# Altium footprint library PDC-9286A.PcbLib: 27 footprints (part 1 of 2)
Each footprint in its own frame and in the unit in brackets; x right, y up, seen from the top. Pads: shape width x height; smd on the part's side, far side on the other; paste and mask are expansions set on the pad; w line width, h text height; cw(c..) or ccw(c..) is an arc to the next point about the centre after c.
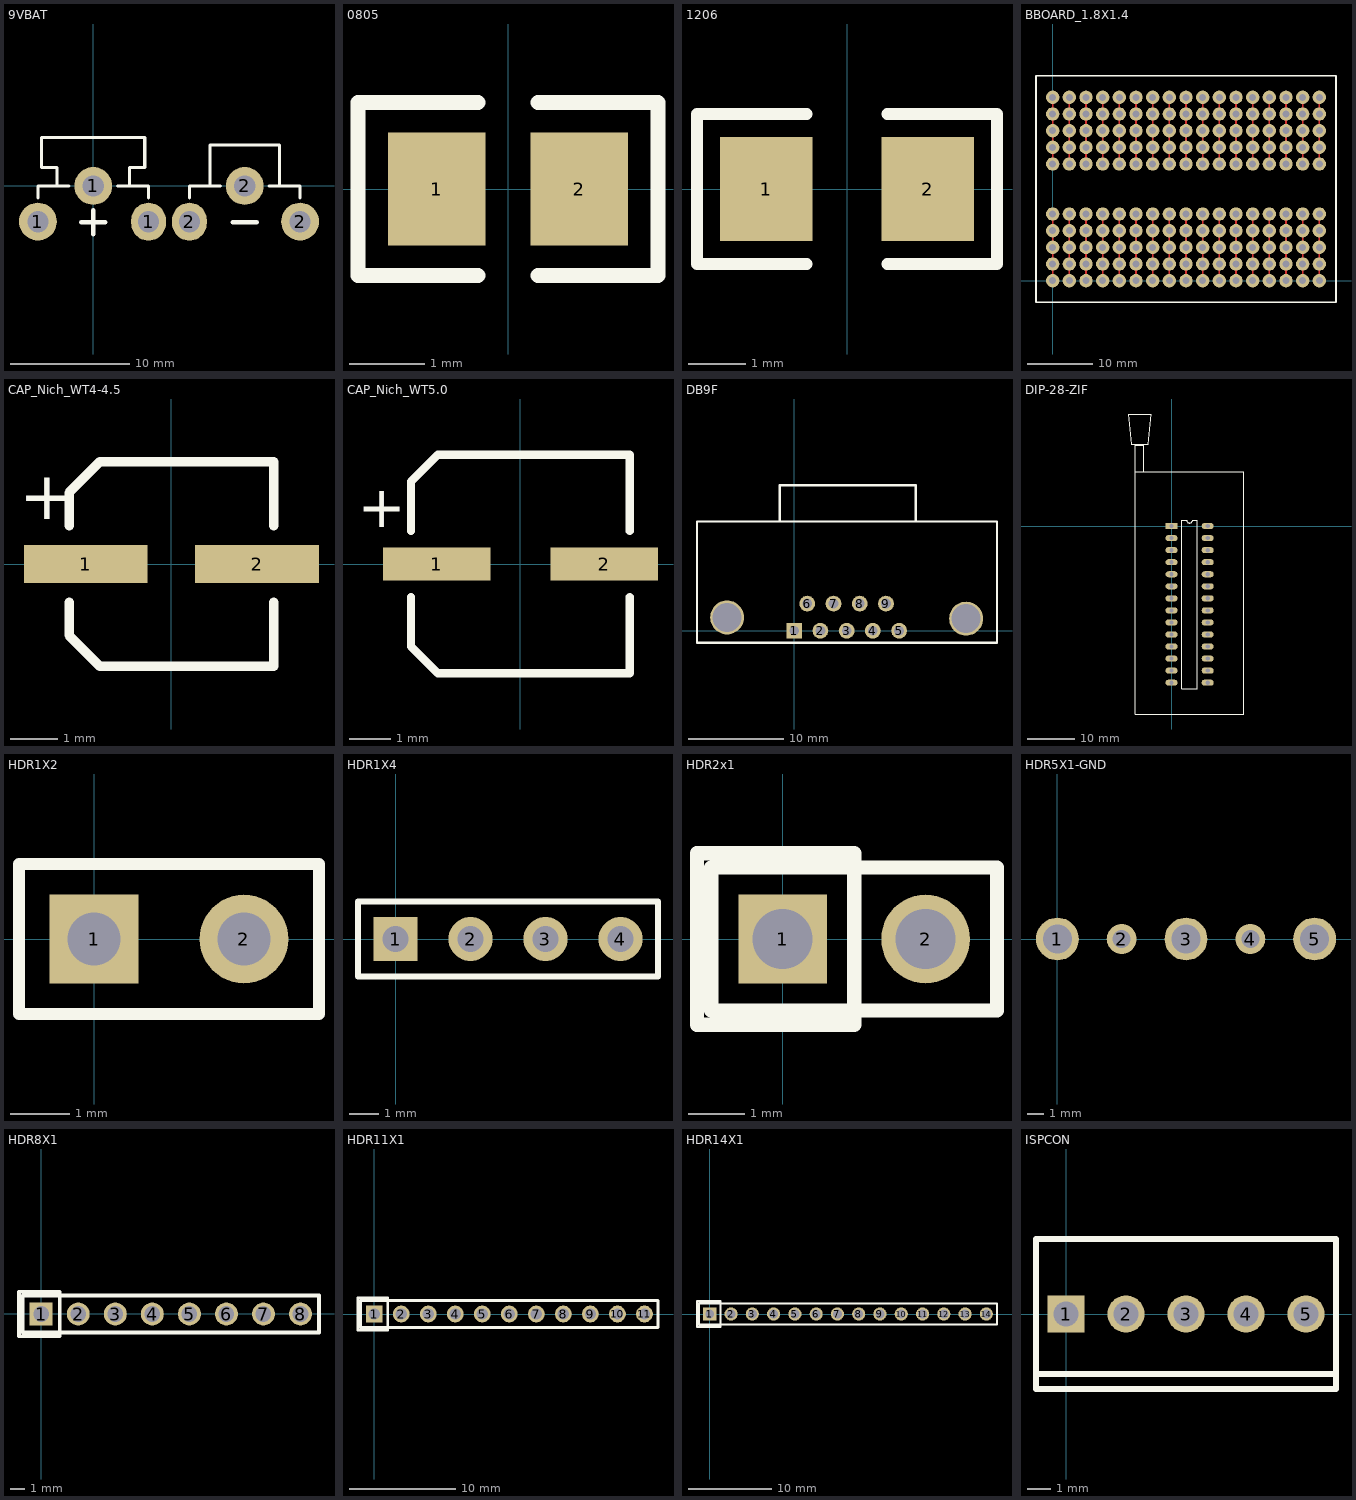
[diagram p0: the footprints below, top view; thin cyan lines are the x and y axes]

## 9VBAT [mil]
pads (6):
  round 125 hole 70: 1(-182.5,-118) 1(0,0) 2(500,0) 2(682.5,-118)
  oval 115x125 hole 70: 1(182.5,-118) 2(317.5,-118)
Top Overlay:
  lines w10: -182.5,-40 -182.5,0 -80,0 ; -120,0 -120,60 -170,60 -170,160 170,160 170,60 120,60 120,0 ; 80,0 182.5,0 182.5,-40 ; 317.5,-40 317.5,0 420,0 ; 385,0 385,135 615,135 615,0 ; 580,0 682.5,0 682.5,-40
  lines w15: -40,-120 40,-120 ; 0,-160 0,-80 ; 460,-120 540,-120

## 0805 [mm]
pads (2):
  rect 1.3x1.5 smd: 1(-0.95,0) 2(0.95,0)
Top Overlay:
  lines w0.2: -0.4,-1.15 -2,-1.15 -2,1.15 -0.4,1.15 ; 0.4,-1.15 2,-1.15 2,1.15 0.4,1.15

## 1206 [mm]
pads (2):
  rect 1.6x1.8 smd: 1(-1.4,0) 2(1.4,0)
Top Overlay:
  lines w0.2: -0.7,-1.3 -2.6,-1.3 -2.6,1.3 -0.7,1.3 ; 0.7,-1.3 2.6,-1.3 2.6,1.3 0.7,1.3

## BBOARD_1.8X1.4 [mil] "28 tie point Breadboard  ( 3M 923273-I )"
pads (170):
  round 80 hole 42: ""(0,0) ""(0,100) ""(0,200) ""(0,300) ""(0,400) ""(0,700) ""(0,800) ""(0,900) ""(0,1000) ""(0,1100) ""(100,0) ""(100,100) ""(100,200) ""(100,300) ""(100,400) ""(100,700) ""(100,800) ""(100,900) ""(100,1000) ""(100,1100) ""(200,0) ""(200,100) ""(200,200) ""(200,300) ""(200,400) ""(200,700) ""(200,800) ""(200,900) ""(200,1000) ""(200,1100) ""(300,0) ""(300,100) ""(300,200) ""(300,300) ""(300,400) ""(300,700) ""(300,800) ""(300,900) ""(300,1000) ""(300,1100) ""(400,0) ""(400,100) ""(400,200) ""(400,300) ""(400,400) ""(400,700) ""(400,800) ""(400,900) ""(400,1000) ""(400,1100) ""(500,0) ""(500,100) ""(500,200) ""(500,300) ""(500,400) ""(500,700) ""(500,800) ""(500,900) ""(500,1000) ""(500,1100) ""(600,0) ""(600,100) ""(600,200) ""(600,300) ""(600,400) ""(600,700) ""(600,800) ""(600,900) ""(600,1000) ""(600,1100) ""(700,0) ""(700,100) ""(700,200) ""(700,300) ""(700,400) ""(700,700) ""(700,800) ""(700,900) ""(700,1000) ""(700,1100) ""(800,0) ""(800,100) ""(800,200) ""(800,300) ""(800,400) ""(800,700) ""(800,800) ""(800,900) ""(800,1000) ""(800,1100) ""(900,0) ""(900,100) ""(900,200) ""(900,300) ""(900,400) ""(900,700) ""(900,800) ""(900,900) ""(900,1000) ""(900,1100) ""(1000,0) ""(1000,100) ""(1000,200) ""(1000,300) ""(1000,400) ""(1000,700) ""(1000,800) ""(1000,900) ""(1000,1000) ""(1000,1100) ""(1100,0) ""(1100,100) ""(1100,200) ""(1100,300) ""(1100,400) ""(1100,700) ""(1100,800) ""(1100,900) ""(1100,1000) ""(1100,1100) ""(1200,0) ""(1200,100) ""(1200,200) ""(1200,300) ""(1200,400) ""(1200,700) ""(1200,800) ""(1200,900) ""(1200,1000) ""(1200,1100) ""(1300,0) ""(1300,100) ""(1300,200) ""(1300,300) ""(1300,400) ""(1300,700) ""(1300,800) ""(1300,900) ""(1300,1000) ""(1300,1100) ""(1400,0) ""(1400,100) ""(1400,200) ""(1400,300) ""(1400,400) ""(1400,700) ""(1400,800) ""(1400,900) ""(1400,1000) ""(1400,1100) ""(1500,0) ""(1500,100) ""(1500,200) ""(1500,300) ""(1500,400) ""(1500,700) ""(1500,800) ""(1500,900) ""(1500,1000) ""(1500,1100) ""(1600,0) ""(1600,100) ""(1600,200) ""(1600,300) ""(1600,400) ""(1600,700) ""(1600,800) ""(1600,900) ""(1600,1000) ""(1600,1100)
Top Layer:
  lines w10: 0,0 0,400 ; 0,700 0,1100 ; 100,0 100,400 ; 100,700 100,1100 ; 200,0 200,400 ; 200,700 200,1100 ; 300,0 300,400 ; 300,700 300,1100 ; 400,0 400,400 ; 400,700 400,1100 ; 500,0 500,400 ; 500,700 500,1100 ; 600,0 600,400 ; 600,700 600,1100 ; 700,0 700,400 ; 700,700 700,1100 ; 800,0 800,400 ; 800,700 800,1100 ; 900,0 900,400 ; 900,700 900,1100 ; 1000,0 1000,400 ; 1000,700 1000,1100 ; 1100,0 1100,400 ; 1100,700 1100,1100 ; 1200,0 1200,400 ; 1200,700 1200,1100 ; 1300,0 1300,400 ; 1300,700 1300,1100 ; 1400,0 1400,400 ; 1400,700 1400,1100 ; 1500,0 1500,400 ; 1500,700 1500,1100 ; 1600,0 1600,400 ; 1600,700 1600,1100
Top Overlay:
  lines w10: -100,-130 -100,1230 1700,1230 1700,-130 -100,-130

## CAP_Nich_WT4-4.5 [mm]
pads (2):
  rect 2.6x0.8 smd: 1(-1.8,0) 2(1.8,0)
Top Overlay:
  lines w0.2: -2.15,-0.8 -2.15,-1.5 -1.5,-2.15 2.15,-2.15 2.15,-0.8 ; -2.15,0.8 -2.15,1.5 -1.5,2.15 2.15,2.15 2.15,0.8
  text "+" at -3.2,0.94 h1.02

## CAP_Nich_WT5.0 [mm]
pads (2):
  rect 2.6x0.8 smd: 1(-2.032,0) 2(2.032,0)
Top Overlay:
  lines w0.2: -2.65,-0.8 -2.65,-2 -2,-2.65 2.65,-2.65 2.65,-0.8 ; -2.65,0.8 -2.65,2 -2,2.65 2.65,2.65 2.65,0.8
  text "+" at -3.937,0.889 h1.02

## DB9F [mil]
pads (11):
  rect 65x65 hole 40: 1(0,0)
  round 65 hole 40: 2(108,0) 3(216,0) 4(324,0) 5(432,0) 6(54,112) 7(162,112) 8(270,112) 9(378,112)
  round 140 hole 120: ""(-276,55) ""(708,50)
Top Overlay:
  lines w10: -60,450 -60,600 500,600 500,450 ; -400,-50 835,-50 835,450 -400,450 -400,-50

## DIP-28-ZIF [mil]
pads (28):
  rect 100x50 hole 35: 1(0,0)
  oval 100x50 hole 35: 2(0,-100) 3(0,-200) 4(0,-300) 5(0,-400) 6(0,-500) 7(0,-600) 8(0,-700) 9(0,-800) 10(0,-900) 11(0,-1000) 12(0,-1100) 13(0,-1200) 14(0,-1300) 15(300,-1300) 16(300,-1200) 17(300,-1100) 18(300,-1000) 19(300,-900) 20(300,-800) 21(300,-700) 22(300,-600) 23(300,-500) 24(300,-400) 25(300,-300) 26(300,-200) 27(300,-100) 28(300,0)
Top Overlay:
  lines w10: -230,450 -230,670 -300,670 -300,450 ; -300,450 600,450 600,-1560 -300,-1560 -300,450 ; -360,930 -335,680 -195,680 -170,930 -360,930 ; 85,-1350 85,50 125,50 ccw(c150,50) 175,50 215,50 215,-1350 85,-1350

## HDR1X2 [mm] "Connector; Header; 2 Position"
pads (2):
  rect 1.5x1.5 hole 0.9: 1(0,0)
  round 1.5 hole 0.9: 2(2.54,0)
Top Overlay:
  lines w0.2: -1.27,-1.27 3.81,-1.27 3.81,1.27 -1.27,1.27 -1.27,-1.27

## HDR1X4 [mm] "Connector; Header; 4 Position"
pads (4):
  rect 1.5x1.5 hole 0.889: 1(0,0)
  round 1.5 hole 0.889: 2(2.54,0) 3(5.08,0) 4(7.62,0)
Top Overlay:
  lines w0.2: -1.27,-1.27 8.89,-1.27 8.89,1.27 -1.27,1.27 -1.27,-1.27

## HDR2x1 [mil]
height 200
pads (2):
  rect 62x62 hole 42: 1(0,0)
  round 62 hole 42: 2(100,0)
Top Overlay:
  lines w10: -60,-60 50,-60 50,60 -60,60 -60,-60 ; -50,-50 -50,50 150,50 150,-50 -50,-50

## HDR5X1-GND [mil]
pads (5):
  round 100 hole 67: 1(0,0) 3(300,0) 5(600,0)
  round 70 hole 42: 2(150,0) 4(450,0)

## HDR8X1 [mil]
pads (8):
  rect 62x62 hole 42: 1(0.12,-0.12)
  round 62 hole 42: 2(100.12,-0.12) 3(200.12,-0.12) 4(300.12,-0.12) 5(400.12,-0.12) 6(500.12,-0.12) 7(600.12,-0.12) 8(700.12,-0.12)
Top Overlay:
  lines w10: -59.88,-60.12 50.12,-60.12 50.12,-50.12 50.12,49.88 50.12,59.88 -59.88,59.88 -59.88,-60.12 ; -49.88,-50.12 750.12,-50.12 750.12,49.88 -49.88,49.88 -49.88,-50.12

## HDR11X1 [mil]
height 500
pads (11):
  rect 62x62 hole 42: 1(0,0)
  round 62 hole 42: 2(100,0) 3(200,0) 4(300,0) 5(400,0) 6(500,0) 7(600,0) 8(700,0) 9(800,0) 10(900,0) 11(1000,0)
Top Overlay:
  lines w10: -60,-60 50,-60 50,60 -60,60 -60,-60 ; -50,-50 1050,-50 1050,50 -50,50 -50,-50

## HDR14X1 [mil]
pads (14):
  rect 62x62 hole 42: 1(0,0)
  round 62 hole 42: 2(100,0) 3(200,0) 4(300,0) 5(400,0) 6(500,0) 7(600,0) 8(700,0) 9(800,0) 10(900,0) 11(1000,0) 12(1100,0) 13(1200,0) 14(1300,0)
Top Overlay:
  lines w10: -60,-60 50,-60 50,60 -60,60 -60,-60 ; -50,-50 -50,50 1350,50 1350,-50 -50,-50

## ISPCON [mil]
pads (5):
  rect 62x62 hole 42: 1(0,0)
  round 62 hole 42: 2(100,0) 3(200,0) 4(300,0) 5(400,0)
Top Overlay:
  lines w10: -50,-100 450,-100 ; -50,-125 450,-125 450,125 -50,125 -50,-125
